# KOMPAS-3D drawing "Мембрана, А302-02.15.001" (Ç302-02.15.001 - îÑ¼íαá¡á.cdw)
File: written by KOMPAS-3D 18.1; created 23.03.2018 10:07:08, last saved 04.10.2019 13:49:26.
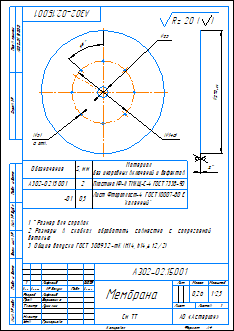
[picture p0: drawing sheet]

Sheet 1: A4, portrait

Document properties: Автор: Милов; Организация: Милов; Полное имя файла: D:\Мембранные насосы\Мембранный электропривод\А302-00.00.000 - ASTRA-302 (МЭ200)\Чертежи ПВХ\А302-02.15.001 - Мембрана.cdw; Масса: 0.264223; Параметр неуказанной шероховатости: Rz 20

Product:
- Part/product: Мембрана  | designation А302-02.15.001
    Масса: 0.264223
    Раздел спецификации: Детали
    Форматы листов документа: A4
- Part/product: Мембрана  | designation А302-01.15.001
    Масса: 0.266387
    Раздел спецификации: Детали
    Форматы листов документа: A4
    source file: ..\3Д ПВХ\А302-01.15.001 - Мембрана.cdw

Title block, sheet 1: Наименование: Мембрана; designation: А302-02.15.001; Масса: 0,26; scale: 1:2,5; Количество листов документа: 1; organisation: АО «Астерион»; Форматы листов документа: A4; stored path: \\192.168.87.28\Konstructor_doc\Мембранные насосы\Мембранный электропривод\А302-00.00.000 - ASTRA-302 (МЭ200)\Чертежи\А302-00.15.001 - Мембрана.cdw; Разработал: Лифлянд; Проверил: Борисенко; Т. контр.: Лучихин; Утвердил: Григорьева

Views: Вид 1, Спереди, Проекционный вид 2
Referenced files in Z:\Мембранные насосы\Мембранный электропривод\А302-00.00.000 - ASTRA-302 (МЭ200)\3Д\: А302-00.15.001 - Мембрана.m3d
Referenced files in D:\Мембранные насосы\Мембранный электропривод\А302-00.00.000 - ASTRA-302 (МЭ200)\3Д ПВХ\: А302-01.15.001 - Мембрана.m3d
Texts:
  См. ТТ
  S, мм
  без инородных включений и дефектов
  Лист Фторопласт-4  ГОСТ 10007-80 Е
  "каленный"
  Пластина ІФ-IІ ТМКЩ-C-4 ГОСТ 7338-90
  Rz 20
  Rz 20 ( )
Dimensions and other numbers on the sheet: 5; 8 отв.; 25; 140; 278; -01; 0,5; 2; 1:2,5; 1; 0,26; 04.10.2019

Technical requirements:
  *Размер для справок.
  Размеры в скобках обработать совместно с сопрягаемой
  деталью.
  Общие допуски ГОСТ 30893.2-mK (H14, h14,  t2/2).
